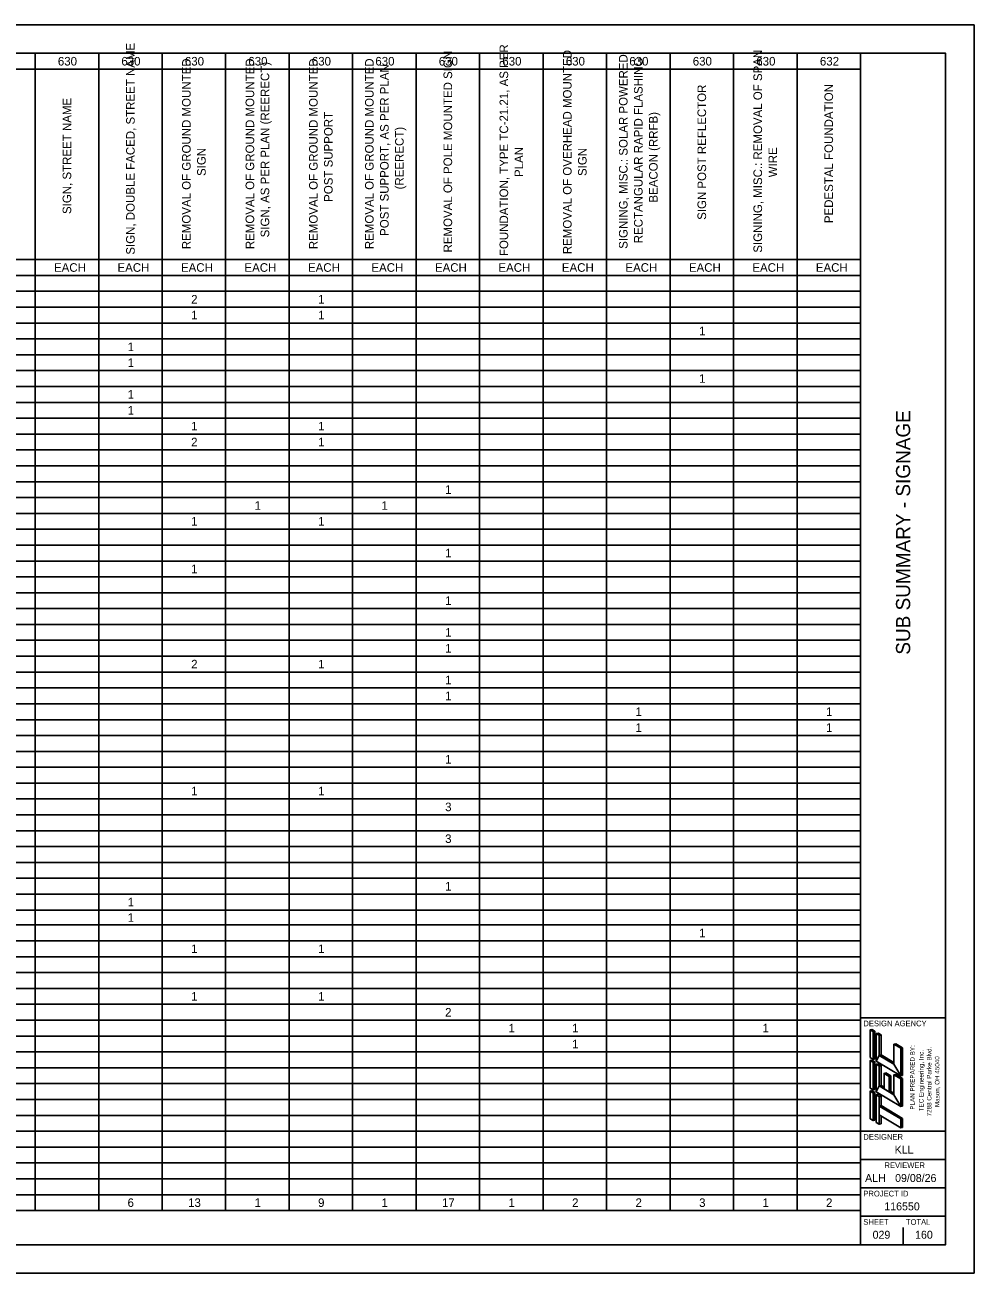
# Model space of a CAD drawing. Extents: x 0 to 34, y 0 to 22.
# Drawn here: x 17.28 to 34, y 0 to 22 of the extents above; entities that cross this region are included whole.
import ezdxf

# ---------------------------------------------------------------- set-up
doc = ezdxf.new("R2010")
doc.units = 0
for name, color, linetype in [('Default', 7, 'Continuous'), ('SH_Border', 7, 'Continuous'), ('SH_Cut_Line', 7, 'Continuous'), ('SH_Data', 7, 'Continuous'), ('SH_Text', 7, 'Continuous')]:
    doc.layers.add(name, color=color, linetype=linetype)

msp = doc.modelspace()

# ---------------------------------------------------------------- linework, layer by layer
at = {"layer": 'SH_Border'}
for p, q in [((32, 0.5), (32, 21.5)), ((32, 4.5), (33.5, 4.5)), ((32, 2.5), (33.5, 2.5)), ((32, 2), (33.5, 2)), ((32, 1.5), (33.5, 1.5)), ((32, 1), (33.5, 1))]:
    msp.add_line(p, q, dxfattribs=at)
msp.add_lwpolyline([(1.5, 21.5), (33.5, 21.5), (33.5, 0.5), (1.5, 0.5)], close=True, dxfattribs=at)
at = {"layer": 'SH_Cut_Line'}
msp.add_lwpolyline([(0, 0), (34, 0), (34, 22), (0, 22)], close=True, dxfattribs=at)
at = {"layer": 'SH_Data'}
for p, q in [((32.75, 3.5), (32.75, 3.5)), ((32.375, 0.675), (32.375, 0.675)), ((32.75, 0.5), (32.75, 0.8))]:
    msp.add_line(p, q, dxfattribs=at)
at = {"layer": 'SH_Text'}
for p, q in [((1.5, 21.5), (32, 21.5)), ((17.457, 21.5), (17.457, 1.101)), ((18.576, 21.5), (18.576, 1.101)), ((19.695, 21.5), (19.695, 1.101)), ((20.813, 21.5), (20.813, 1.101)), ((21.932, 21.5), (21.932, 1.101)), ((23.051, 21.5), (23.051, 1.101)), ((24.169, 21.5), (24.169, 1.101)), ((25.288, 21.5), (25.288, 1.101)), ((26.407, 21.5), (26.407, 1.101)), ((27.525, 21.5), (27.525, 1.101)), ((28.644, 21.5), (28.644, 1.101)), ((29.763, 21.5), (29.763, 1.101)), ((30.881, 21.5), (30.881, 1.101)), ((32, 21.5), (32, 1.101)), ((10.745, 21.221), (32, 21.221)), ((10.745, 17.865), (32, 17.865)), ((1.5, 17.585), (32, 17.585)), ((1.5, 17.305), (32, 17.305)), ((1.5, 17.026), (32, 17.026)), ((1.5, 16.746), (32, 16.746)), ((8.097, 16.466), (32, 16.466)), ((8.097, 16.187), (32, 16.187)), ((1.5, 15.907), (32, 15.907)), ((8.097, 15.627), (32, 15.627)), ((8.097, 15.348), (32, 15.348)), ((1.5, 15.068), (32, 15.068)), ((1.5, 14.788), (32, 14.788)), ((1.5, 14.509), (32, 14.509)), ((1.5, 14.229), (32, 14.229)), ((1.5, 13.949), (32, 13.949)), ((1.5, 13.67), (32, 13.67)), ((1.5, 13.39), (32, 13.39)), ((1.5, 13.11), (32, 13.11)), ((1.5, 12.831), (32, 12.831)), ((1.5, 12.551), (32, 12.551)), ((1.5, 12.271), (32, 12.271)), ((1.5, 11.992), (32, 11.992)), ((1.5, 11.712), (32, 11.712)), ((1.5, 11.432), (32, 11.432)), ((1.5, 11.153), (32, 11.153)), ((1.5, 10.873), (32, 10.873)), ((1.5, 10.593), (32, 10.593)), ((1.5, 10.314), (32, 10.314)), ((1.5, 10.034), (32, 10.034)), ((1.5, 9.754), (32, 9.754)), ((1.5, 9.475), (32, 9.475)), ((1.5, 9.195), (32, 9.195)), ((1.5, 8.915), (32, 8.915)), ((1.5, 8.636), (32, 8.636)), ((1.5, 8.356), (32, 8.356)), ((8.097, 8.076), (32, 8.076)), ((1.5, 7.797), (32, 7.797)), ((1.5, 7.517), (32, 7.517)), ((8.097, 7.237), (32, 7.237)), ((1.5, 6.958), (32, 6.958)), ((1.5, 6.678), (32, 6.678)), ((8.097, 6.398), (32, 6.398)), ((8.097, 6.135), (32, 6.135)), ((1.5, 5.856), (32, 5.856)), ((1.5, 5.576), (32, 5.576)), ((1.5, 5.296), (32, 5.296)), ((1.5, 5.017), (32, 5.017)), ((1.5, 4.737), (32, 4.737)), ((1.5, 4.457), (32, 4.457)), ((32.169, 4.285), (32.201, 4.294)), ((32.169, 3.799), (32.169, 4.285)), ((32.223, 4.253), (32.169, 4.285)), ((32.255, 4.261), (32.201, 4.294)), ((32.223, 4.253), (32.255, 4.261)), ((32.223, 3.767), (32.223, 4.253)), ((32.255, 3.775), (32.255, 4.261)), ((32.277, 4.221), (32.309, 4.229)), ((32.331, 4.188), (32.277, 4.221)), ((32.277, 3.735), (32.277, 4.221)), ((32.309, 4.229), (32.363, 4.196)), ((32.331, 4.188), (32.363, 4.196)), ((32.331, 3.837), (32.331, 4.188)), ((32.363, 4.196), (32.363, 3.845)), ((8.097, 4.178), (32, 4.178)), ((32.587, 4.034), (32.62, 4.042)), ((32.587, 3.683), (32.587, 4.034)), ((32.709, 3.961), (32.587, 4.034)), ((32.62, 4.042), (32.741, 3.97)), ((32.709, 3.961), (32.741, 3.97)), ((32.709, 3.475), (32.709, 3.961)), ((32.741, 3.97), (32.741, 3.484)), ((1.5, 3.898), (32, 3.898)), ((32.223, 3.767), (32.169, 3.799)), ((32.169, 3.745), (32.201, 3.754)), ((32.169, 3.259), (32.169, 3.745)), ((32.223, 3.713), (32.169, 3.745)), ((32.255, 3.722), (32.201, 3.754)), ((32.223, 3.767), (32.255, 3.775)), ((32.331, 3.837), (32.363, 3.845)), ((32.587, 3.683), (32.331, 3.837)), ((32.363, 3.845), (32.587, 3.711)), ((1.5, 3.618), (32, 3.618)), ((32.223, 3.713), (32.255, 3.722)), ((32.223, 3.227), (32.223, 3.713)), ((32.255, 3.236), (32.255, 3.722)), ((32.709, 3.475), (32.277, 3.735)), ((32.277, 3.681), (32.309, 3.689)), ((32.277, 3.195), (32.277, 3.681)), ((32.331, 3.648), (32.277, 3.681)), ((32.309, 3.689), (32.363, 3.656)), ((32.331, 3.648), (32.363, 3.656)), ((32.331, 3.297), (32.331, 3.648)), ((32.363, 3.656), (32.363, 3.305)), ((32.415, 3.519), (32.448, 3.527)), ((32.448, 3.527), (32.535, 3.474)), ((1.5, 3.339), (32, 3.339)), ((32.331, 3.297), (32.363, 3.305)), ((32.363, 3.305), (32.415, 3.274)), ((32.415, 3.519), (32.415, 3.247)), ((32.415, 3.519), (32.503, 3.466)), ((32.503, 3.466), (32.535, 3.474)), ((32.503, 3.466), (32.503, 3.194)), ((32.535, 3.474), (32.535, 3.202)), ((32.587, 3.494), (32.62, 3.502)), ((32.587, 3.143), (32.587, 3.494)), ((32.709, 3.421), (32.587, 3.494)), ((32.62, 3.502), (32.741, 3.43)), ((32.709, 3.475), (32.741, 3.484)), ((32.709, 3.421), (32.741, 3.43)), ((32.709, 2.935), (32.709, 3.421)), ((32.741, 3.43), (32.741, 2.944)), ((32.223, 3.227), (32.169, 3.259)), ((32.169, 3.205), (32.201, 3.215)), ((32.169, 2.719), (32.169, 3.205)), ((32.223, 3.173), (32.169, 3.205)), ((32.255, 3.181), (32.201, 3.215)), ((32.222, 3.173), (32.255, 3.181)), ((32.223, 3.227), (32.255, 3.236)), ((32.223, 2.687), (32.223, 3.173)), ((32.255, 2.695), (32.255, 3.181)), ((32.709, 2.935), (32.277, 3.195)), ((32.277, 3.141), (32.309, 3.151)), ((32.331, 3.108), (32.277, 3.141)), ((32.277, 2.655), (32.277, 3.141)), ((32.309, 3.151), (32.363, 3.116)), ((32.415, 3.247), (32.331, 3.297)), ((32.331, 3.108), (32.363, 3.116)), ((32.331, 2.944), (32.331, 3.108)), ((32.363, 3.116), (32.363, 2.952)), ((32.503, 3.194), (32.535, 3.202)), ((32.587, 3.143), (32.503, 3.194)), ((32.535, 3.202), (32.587, 3.171)), ((1.5, 3.059), (32, 3.059)), ((32.331, 2.944), (32.363, 2.952)), ((32.331, 2.944), (32.709, 2.717)), ((32.363, 2.952), (32.741, 2.725)), ((32.709, 2.935), (32.741, 2.944)), ((1.5, 2.779), (32, 2.779)), ((32.223, 2.687), (32.169, 2.719)), ((32.223, 2.687), (32.255, 2.695)), ((32.331, 2.622), (32.277, 2.655)), ((32.331, 2.787), (32.709, 2.56)), ((32.331, 2.622), (32.331, 2.787)), ((32.363, 2.63), (32.363, 2.767)), ((32.709, 2.717), (32.741, 2.725)), ((32.709, 2.56), (32.709, 2.717)), ((32.741, 2.725), (32.741, 2.568)), ((1.5, 2.5), (32, 2.5)), ((32.331, 2.622), (32.363, 2.63)), ((32.709, 2.56), (32.741, 2.568)), ((1.5, 2.22), (32, 2.22)), ((1.5, 1.94), (32, 1.94)), ((1.5, 1.661), (32, 1.661)), ((1.5, 1.381), (32, 1.381)), ((1.5, 1.101), (32, 1.101))]:
    msp.add_line(p, q, dxfattribs=at)
for points in [[(32.169, 3.799), (32.223, 3.767), (32.223, 4.253), (32.169, 4.285)], [(32.277, 3.735), (32.331, 3.837), (32.331, 4.188), (32.277, 4.221)], [(32.709, 3.475), (32.587, 3.683), (32.587, 4.034), (32.709, 3.961)], [(32.169, 3.259), (32.223, 3.227), (32.223, 3.713), (32.169, 3.745)], [(32.277, 3.735), (32.331, 3.837), (32.587, 3.683), (32.709, 3.475)], [(32.277, 3.195), (32.331, 3.297), (32.331, 3.648), (32.277, 3.681)], [(32.415, 3.247), (32.415, 3.519), (32.503, 3.466), (32.503, 3.194)], [(32.709, 2.935), (32.587, 3.143), (32.587, 3.494), (32.709, 3.421)], [(32.169, 2.719), (32.223, 2.687), (32.223, 3.173), (32.169, 3.205)], [(32.277, 3.195), (32.331, 3.297), (32.587, 3.143), (32.709, 2.935)], [(32.277, 2.655), (32.331, 2.622), (32.331, 3.108), (32.277, 3.141)], [(32.331, 2.787), (32.331, 2.944), (32.709, 2.717), (32.709, 2.56)]]:
    msp.add_lwpolyline(points, close=True, dxfattribs=at)

# ---------------------------------------------------------------- texts
at = {"layer": 'Default'}
for s, p in [('PLAN PREPARED BY:', (32.954, 2.88)), ('TEC Engineering, Inc.', (33.11, 2.851)), ('7288 Central Parke Blvd.', (33.25, 2.762)), ('Mason, OH 45040', (33.39, 2.925))]:
    msp.add_text(s, height=0.08, rotation=90, dxfattribs=at).set_placement(p)
at = {"layer": 'SH_Data'}
msp.add_text('SUB SUMMARY - SIGNAGE', height=0.25, rotation=90, dxfattribs=at).set_placement((32.875, 10.9))
for s, height, p in [('DESIGN AGENCY', 0.1, (32.05, 4.35)), ('DESIGNER', 0.1, (32.05, 2.35)), ('KLL', 0.14, (32.601, 2.105)), ('REVIEWER', 0.1, (32.422, 1.85)), ('ALH', 0.14, (32.08, 1.605)), ('09/08/26', 0.14, (32.609, 1.605)), ('PROJECT ID', 0.1, (32.05, 1.35)), ('116550', 0.14, (32.419, 1.105)), ('SHEET', 0.1, (32.05, 0.85)), ('TOTAL', 0.1, (32.8, 0.85)), ('029', 0.14, (32.213, 0.605)), ('160', 0.14, (32.961, 0.605))]:
    msp.add_text(s, height=height, dxfattribs=at).set_placement(p)
at = {"layer": 'SH_Text'}
for s, height, p in [('SIGN, DOUBLE FACED, STREET NAME', 0.15135, (19.211, 17.951)), ('FOUNDATION, TYPE TC-21.21, AS PER ', 0.15135, (25.791, 17.926)), ('REMOVAL OF GROUND MOUNTED ', 0.15135, (20.197, 18.048)), ('REMOVAL OF GROUND MOUNTED ', 0.15135, (21.316, 18.048)), ('REMOVAL OF GROUND MOUNTED ', 0.15135, (22.435, 18.048)), ('REMOVAL OF GROUND MOUNTED ', 0.15135, (23.421, 18.048)), ('REMOVAL OF POLE MOUNTED SIGN', 0.15135, (24.804, 17.99)), ('REMOVAL OF OVERHEAD MOUNTED ', 0.15135, (26.909, 17.96)), ('SIGNING, MISC.: SOLAR POWERED ', 0.15135, (27.895, 18.054)), ('RECTANGULAR RAPID FLASHING ', 0.15135, (28.16, 18.152)), ('SIGNING, MISC.: REMOVAL OF SPAN ', 0.15135, (30.265, 17.986)), ('SIGN, AS PER PLAN (REERECT)', 0.15135, (21.581, 18.256)), ('POST SUPPORT, AS PER PLAN ', 0.15135, (23.686, 18.282)), ('SIGN POST REFLECTOR', 0.15135, (29.279, 18.565)), ('PEDESTAL FOUNDATION', 0.15135, (31.516, 18.507)), ('SIGN, STREET NAME', 0.15135, (18.092, 18.668)), ('POST SUPPORT', 0.15135, (22.699, 18.882)), ('BEACON (RRFB)', 0.15135, (28.425, 18.869)), ('(REERECT)', 0.1513, (23.951, 19.102)), ('SIGN', 0.1513, (20.462, 19.338)), ('PLAN', 0.1513, (26.055, 19.32)), ('SIGN', 0.1513, (27.174, 19.338)), ('WIRE', 0.1513, (30.53, 19.315))]:
    msp.add_text(s, height=height, rotation=90, dxfattribs=at).set_placement(p)
for s, height, p in [('630', 0.1513, (17.857, 21.285)), ('630', 0.1513, (18.976, 21.285)), ('630', 0.1513, (20.095, 21.285)), ('630', 0.1513, (21.213, 21.285)), ('630', 0.1513, (22.332, 21.285)), ('630', 0.1513, (23.451, 21.285)), ('630', 0.1513, (24.569, 21.285)), ('630', 0.1513, (25.688, 21.285)), ('630', 0.1513, (26.807, 21.285)), ('630', 0.1513, (27.925, 21.285)), ('630', 0.1513, (29.044, 21.285)), ('630', 0.1513, (30.163, 21.285)), ('632', 0.1513, (31.284, 21.285)), ('EACH', 0.1513, (17.789, 17.649)), ('EACH', 0.1513, (18.908, 17.649)), ('EACH', 0.1513, (20.026, 17.649)), ('EACH', 0.1513, (21.145, 17.649)), ('EACH', 0.1513, (22.264, 17.649)), ('EACH', 0.1513, (23.382, 17.649)), ('EACH', 0.1513, (24.501, 17.649)), ('EACH', 0.1513, (25.62, 17.649)), ('EACH', 0.1513, (26.738, 17.649)), ('EACH', 0.1513, (27.857, 17.649)), ('EACH', 0.1513, (28.976, 17.649)), ('EACH', 0.1513, (30.094, 17.649)), ('EACH', 0.1513, (31.213, 17.649)), ('2', 0.151, (20.206, 17.09)), ('1', 0.151, (22.443, 17.09)), ('1', 0.151, (20.205, 16.81)), ('1', 0.151, (22.443, 16.81)), ('1', 0.151, (29.155, 16.531)), ('1', 0.151, (19.087, 16.251)), ('1', 0.151, (19.087, 15.971)), ('1', 0.151, (29.155, 15.692)), ('1', 0.151, (19.087, 15.412)), ('1', 0.151, (19.087, 15.132)), ('1', 0.151, (20.205, 14.853)), ('1', 0.151, (22.443, 14.853)), ('2', 0.151, (20.206, 14.573)), ('1', 0.151, (22.443, 14.573)), ('1', 0.151, (24.68, 13.734)), ('1', 0.151, (21.324, 13.454)), ('1', 0.151, (23.561, 13.454)), ('1', 0.151, (20.205, 13.175)), ('1', 0.151, (22.443, 13.175)), ('1', 0.151, (24.68, 12.615)), ('1', 0.151, (20.205, 12.336)), ('1', 0.151, (24.68, 11.776)), ('1', 0.151, (24.68, 11.217)), ('1', 0.151, (24.68, 10.937)), ('2', 0.151, (20.206, 10.658)), ('1', 0.151, (22.443, 10.658)), ('1', 0.151, (24.68, 10.378)), ('1', 0.151, (24.68, 10.098)), ('1', 0.151, (28.036, 9.819)), ('1', 0.151, (31.392, 9.819)), ('1', 0.151, (28.036, 9.539)), ('1', 0.151, (31.392, 9.539)), ('1', 0.151, (24.68, 8.98)), ('1', 0.151, (20.205, 8.42)), ('1', 0.151, (22.443, 8.42)), ('3', 0.151, (24.681, 8.141)), ('3', 0.151, (24.681, 7.581)), ('1', 0.151, (24.68, 6.742)), ('1', 0.151, (19.087, 6.463)), ('1', 0.151, (19.087, 6.191)), ('1', 0.151, (29.155, 5.92)), ('1', 0.151, (20.205, 5.64)), ('1', 0.151, (22.443, 5.64)), ('1', 0.151, (20.205, 4.801)), ('1', 0.151, (22.443, 4.801)), ('2', 0.151, (24.68, 4.521)), ('1', 0.151, (25.799, 4.242)), ('1', 0.151, (26.917, 4.242)), ('1', 0.151, (30.273, 4.242)), ('1', 0.151, (26.917, 3.962)), ('6', 0.151, (19.085, 1.165)), ('13', 0.1513, (20.152, 1.165)), ('1', 0.151, (21.324, 1.165)), ('9', 0.151, (22.442, 1.165)), ('1', 0.151, (23.561, 1.165)), ('17', 0.1513, (24.625, 1.165)), ('1', 0.151, (25.799, 1.165)), ('2', 0.151, (26.918, 1.165)), ('2', 0.151, (28.036, 1.165)), ('3', 0.151, (29.156, 1.165)), ('1', 0.151, (30.273, 1.165)), ('2', 0.151, (31.392, 1.165))]:
    msp.add_text(s, height=height, dxfattribs=at).set_placement(p)

doc.saveas('drawing.dxf')
